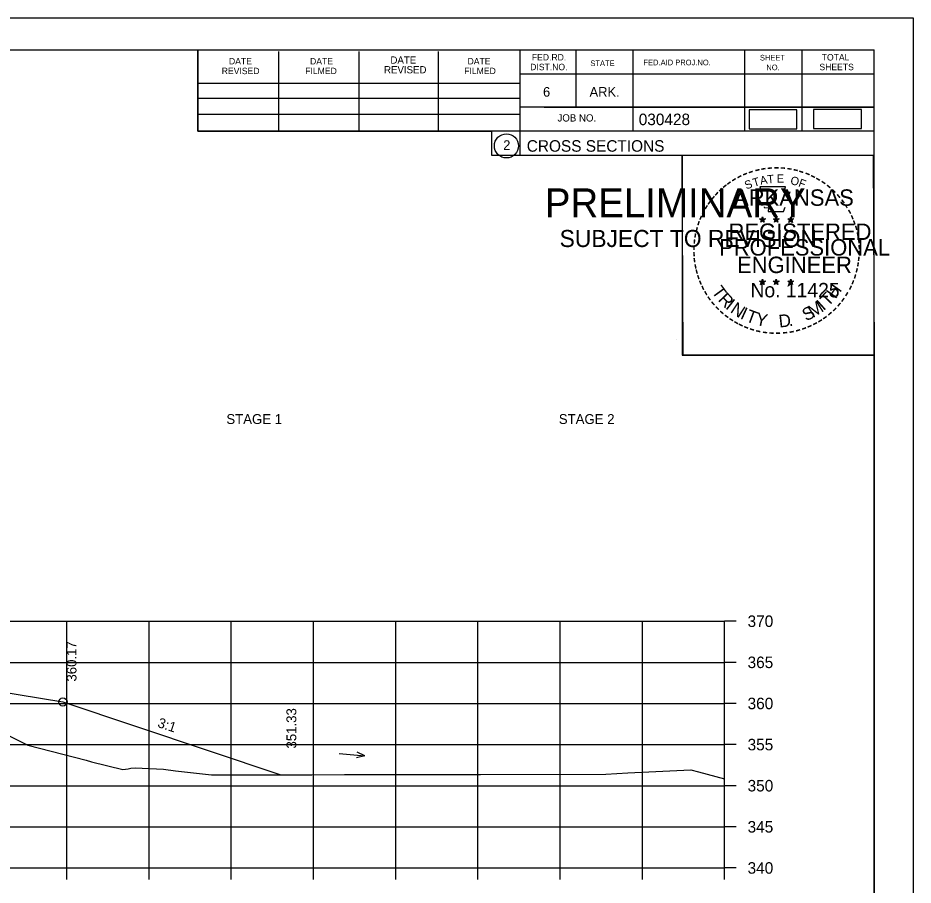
# Model space of a CAD drawing. Extents: x 1374859 to 1376773, y 382242 to 389804.
# Drawn here: x 1376188.6 to 1376297.5, y 385123 to 385228.5 of the extents above; entities that cross this region are included whole.
import ezdxf

# ---------------------------------------------------------------- set-up
doc = ezdxf.new("R2010")
doc.units = 0
for name, color, linetype in [('R_Axis', 7, 'Continuous'), ('R_Axis Annot', 7, 'Continuous'), ('R_Border', 7, 'Continuous'), ('R_Border PE', 7, 'Continuous'), ('R_Border Prem', 7, 'Continuous'), ('R_Exist Surface', 7, 'Continuous'), ('R_Fin Surface', 7, 'Continuous'), ('R_Grid', 7, 'Continuous'), ('R_MOT', 7, 'Continuous'), ('R_No Plot', 7, 'Continuous'), ('R_Water Annot', 7, 'Continuous'), ('R_Xsect Elev', 7, 'Continuous'), ('R_Xsect Slope', 7, 'Continuous')]:
    doc.layers.add(name, color=color, linetype=linetype)

msp = doc.modelspace()

# ---------------------------------------------------------------- linework, layer by layer
at = {"layer": 'R_Axis'}
for p, q in [((1376274.57, 385125.11), (1376274.57, 385155.11)), ((1376275.97, 385155.11), (1376274.57, 385155.11)), ((1376275.97, 385150.11), (1376274.57, 385150.11)), ((1376275.97, 385145.11), (1376274.57, 385145.11)), ((1376275.97, 385140.11), (1376274.57, 385140.11)), ((1376275.97, 385135.11), (1376274.57, 385135.11)), ((1376275.97, 385130.11), (1376274.57, 385130.11)), ((1375994.57, 385125.11), (1376274.57, 385125.11)), ((1376194.57, 385123.71), (1376194.57, 385125.11)), ((1376204.57, 385123.71), (1376204.57, 385125.11)), ((1376214.57, 385123.71), (1376214.57, 385125.11)), ((1376224.57, 385123.71), (1376224.57, 385125.11)), ((1376234.57, 385123.71), (1376234.57, 385125.11)), ((1376244.57, 385123.71), (1376244.57, 385125.11)), ((1376254.57, 385123.71), (1376254.57, 385125.11)), ((1376264.57, 385123.71), (1376264.57, 385125.11)), ((1376274.57, 385123.71), (1376274.57, 385125.11)), ((1376275.97, 385125.11), (1376274.57, 385125.11))]:
    msp.add_line(p, q, dxfattribs=at)
at = {"layer": 'R_Border'}
for p, q in [((1375976.57, 385224.57), (1376292.75, 385224.57)), ((1376210.49, 385214.69), (1376210.49, 385224.57)), ((1376220.35, 385214.69), (1376220.35, 385224.37)), ((1376230.11, 385214.69), (1376230.11, 385224.37)), ((1376239.79, 385214.69), (1376239.79, 385224.37)), ((1376249.65, 385224.57), (1376249.65, 385211.77)), ((1376256.49, 385224.57), (1376256.49, 385217.63)), ((1376263.43, 385224.57), (1376263.43, 385214.69)), ((1376277.01, 385224.57), (1376277.01, 385214.69)), ((1376283.95, 385224.57), (1376283.95, 385214.69)), ((1376292.75, 385019.11), (1376292.75, 385224.57)), ((1376292.75, 385221.63), (1376249.65, 385221.63)), ((1376292.75, 385221.65), (1376292.75, 385221.65)), ((1376210.49, 385220.55), (1376249.65, 385220.55)), ((1376210.49, 385218.69), (1376249.65, 385218.69)), ((1376292.75, 385217.63), (1376249.65, 385217.63)), ((1376252.61, 385217.63), (1376292.75, 385217.63)), ((1376210.49, 385214.69), (1376210.49, 385216.75)), ((1376210.49, 385216.75), (1376249.65, 385216.75)), ((1376292.75, 385214.69), (1376210.49, 385214.69)), ((1376249.65, 385211.77), (1376292.75, 385211.77))]:
    msp.add_line(p, q, dxfattribs=at)
msp.add_circle((1376248.04, 385212.91), 1.47, dxfattribs=at)
at = {"layer": 'R_Border PE'}
for p, q in [((1376279.18, 385204.28), (1376279.14, 385204.03)), ((1376279.18, 385203.92), (1376279.18, 385204.28)), ((1376279.18, 385204.28), (1376279.23, 385204.03)), ((1376280.85, 385204.28), (1376280.81, 385204.03)), ((1376280.85, 385203.92), (1376280.85, 385204.28)), ((1376280.85, 385204.28), (1376280.9, 385204.03)), ((1376282.62, 385204.27), (1376282.58, 385204.02)), ((1376282.62, 385203.91), (1376282.62, 385204.27)), ((1376282.62, 385204.27), (1376282.67, 385204.02)), ((1376278.84, 385204.03), (1376279.18, 385203.92)), ((1376278.84, 385204.03), (1376279.09, 385203.98)), ((1376278.84, 385204.03), (1376279.07, 385203.91)), ((1376278.97, 385203.62), (1376279.18, 385203.92)), ((1376278.97, 385203.62), (1376279.09, 385203.87)), ((1376278.97, 385203.62), (1376279.18, 385203.84)), ((1376279.53, 385204.03), (1376279.18, 385203.92)), ((1376279.4, 385203.62), (1376279.18, 385203.92)), ((1376279.4, 385203.62), (1376279.18, 385203.84)), ((1376279.53, 385204.03), (1376279.25, 385203.98)), ((1376279.4, 385203.62), (1376279.26, 385203.91)), ((1376279.53, 385204.03), (1376279.33, 385203.93)), ((1376280.51, 385204.03), (1376280.85, 385203.92)), ((1376280.51, 385204.03), (1376280.76, 385203.98)), ((1376280.51, 385204.03), (1376280.74, 385203.91)), ((1376280.64, 385203.62), (1376280.85, 385203.92)), ((1376280.64, 385203.62), (1376280.76, 385203.87)), ((1376280.64, 385203.62), (1376280.85, 385203.84)), ((1376281.2, 385204.03), (1376280.85, 385203.92)), ((1376281.07, 385203.62), (1376280.85, 385203.92)), ((1376281.07, 385203.62), (1376280.85, 385203.84)), ((1376281.2, 385204.03), (1376280.92, 385203.98)), ((1376281.07, 385203.62), (1376280.93, 385203.91)), ((1376281.2, 385204.03), (1376281, 385203.93)), ((1376282.27, 385204.02), (1376282.62, 385203.91)), ((1376282.27, 385204.02), (1376282.52, 385203.97)), ((1376282.27, 385204.02), (1376282.51, 385203.9)), ((1376282.4, 385203.61), (1376282.62, 385203.91)), ((1376282.4, 385203.61), (1376282.53, 385203.85)), ((1376282.4, 385203.61), (1376282.62, 385203.83)), ((1376282.97, 385204.02), (1376282.62, 385203.91)), ((1376282.83, 385203.61), (1376282.62, 385203.91)), ((1376282.83, 385203.61), (1376282.62, 385203.82)), ((1376282.97, 385204.02), (1376282.68, 385203.97)), ((1376282.83, 385203.61), (1376282.69, 385203.9)), ((1376282.97, 385204.02), (1376282.76, 385203.92)), ((1376279.18, 385196.71), (1376279.14, 385196.46)), ((1376279.18, 385196.35), (1376279.18, 385196.71)), ((1376279.18, 385196.71), (1376279.23, 385196.46)), ((1376280.85, 385196.71), (1376280.81, 385196.46)), ((1376280.85, 385196.35), (1376280.85, 385196.71)), ((1376280.85, 385196.71), (1376280.9, 385196.46)), ((1376282.62, 385196.7), (1376282.58, 385196.45)), ((1376282.62, 385196.34), (1376282.62, 385196.7)), ((1376282.62, 385196.7), (1376282.67, 385196.45)), ((1376278.83, 385196.46), (1376279.18, 385196.35)), ((1376278.83, 385196.46), (1376279.08, 385196.41)), ((1376278.83, 385196.46), (1376279.07, 385196.33)), ((1376278.96, 385196.05), (1376279.18, 385196.35)), ((1376278.96, 385196.05), (1376279.09, 385196.29)), ((1376278.96, 385196.05), (1376279.18, 385196.27)), ((1376279.53, 385196.46), (1376279.18, 385196.35)), ((1376279.39, 385196.05), (1376279.18, 385196.35)), ((1376279.39, 385196.05), (1376279.18, 385196.26)), ((1376279.53, 385196.46), (1376279.24, 385196.41)), ((1376279.39, 385196.05), (1376279.26, 385196.34)), ((1376279.53, 385196.46), (1376279.32, 385196.35)), ((1376280.5, 385196.46), (1376280.85, 385196.35)), ((1376280.5, 385196.46), (1376280.75, 385196.41)), ((1376280.5, 385196.46), (1376280.74, 385196.33)), ((1376280.63, 385196.05), (1376280.85, 385196.35)), ((1376280.63, 385196.05), (1376280.76, 385196.29)), ((1376280.63, 385196.05), (1376280.85, 385196.27)), ((1376281.2, 385196.46), (1376280.85, 385196.35)), ((1376281.06, 385196.05), (1376280.85, 385196.35)), ((1376281.06, 385196.05), (1376280.85, 385196.26)), ((1376281.2, 385196.46), (1376280.91, 385196.41)), ((1376281.06, 385196.05), (1376280.93, 385196.34)), ((1376281.2, 385196.46), (1376280.99, 385196.35)), ((1376282.27, 385196.45), (1376282.62, 385196.34)), ((1376282.27, 385196.45), (1376282.52, 385196.4)), ((1376282.27, 385196.45), (1376282.5, 385196.32)), ((1376282.4, 385196.04), (1376282.62, 385196.34)), ((1376282.4, 385196.04), (1376282.53, 385196.28)), ((1376282.4, 385196.04), (1376282.61, 385196.26)), ((1376282.83, 385196.04), (1376282.61, 385196.25)), ((1376282.96, 385196.45), (1376282.62, 385196.34)), ((1376282.83, 385196.04), (1376282.62, 385196.34)), ((1376282.96, 385196.45), (1376282.68, 385196.4)), ((1376282.83, 385196.04), (1376282.69, 385196.33)), ((1376282.96, 385196.45), (1376282.76, 385196.34))]:
    msp.add_line(p, q, dxfattribs=at)
for points in [[(1376278.88, 385207.91), (1376279.15, 385207.08)], [(1376282.39, 385206.99), (1376282.53, 385207.27), (1376281.84, 385207.25), (1376281.99, 385207.91), (1376278.88, 385207.91)], [(1376279.37, 385205.48), (1376279.37, 385205.4), (1376279.93, 385205.38), (1376279.88, 385204.91), (1376281.75, 385204.91), (1376281.95, 385205.44)], [(1376279.18, 385204.28), (1376279.4, 385203.62), (1376278.84, 385204.03), (1376279.53, 385204.03), (1376278.97, 385203.62), (1376279.18, 385204.28)], [(1376280.85, 385204.28), (1376281.07, 385203.62), (1376280.51, 385204.03), (1376281.2, 385204.03), (1376280.64, 385203.62), (1376280.85, 385204.28)], [(1376282.62, 385204.27), (1376282.83, 385203.61), (1376282.27, 385204.02), (1376282.97, 385204.02), (1376282.4, 385203.61), (1376282.62, 385204.27)], [(1376279.18, 385196.71), (1376279.39, 385196.05), (1376278.83, 385196.46), (1376279.53, 385196.46), (1376278.96, 385196.05), (1376279.18, 385196.71)], [(1376280.85, 385196.71), (1376281.06, 385196.05), (1376280.5, 385196.46), (1376281.2, 385196.46), (1376280.63, 385196.05), (1376280.85, 385196.71)], [(1376282.62, 385196.7), (1376282.83, 385196.04), (1376282.27, 385196.45), (1376282.96, 385196.45), (1376282.4, 385196.04), (1376282.62, 385196.7)]]:
    msp.add_lwpolyline(points, dxfattribs=at)
for centre, radius in [((1376279.18, 385203.92), 0.172), ((1376279.18, 385203.92), 0.145), ((1376279.18, 385203.92), 0.116), ((1376279.18, 385203.92), 0.0991), ((1376279.18, 385203.92), 0.0747), ((1376279.18, 385203.92), 0.0495), ((1376279.18, 385203.92), 0.0296), ((1376280.85, 385203.92), 0.172), ((1376280.85, 385203.92), 0.145), ((1376280.85, 385203.92), 0.116), ((1376280.85, 385203.92), 0.0991), ((1376280.85, 385203.92), 0.0747), ((1376280.85, 385203.92), 0.0495), ((1376280.85, 385203.92), 0.0296), ((1376282.62, 385203.91), 0.172), ((1376282.62, 385203.91), 0.145), ((1376282.62, 385203.91), 0.116), ((1376282.62, 385203.91), 0.0991), ((1376282.62, 385203.91), 0.0747), ((1376282.62, 385203.91), 0.0495), ((1376282.62, 385203.91), 0.0296), ((1376279.18, 385196.34), 0.172), ((1376279.18, 385196.34), 0.145), ((1376279.18, 385196.34), 0.116), ((1376279.18, 385196.34), 0.0991), ((1376279.18, 385196.34), 0.0747), ((1376279.18, 385196.34), 0.0495), ((1376279.18, 385196.34), 0.0296), ((1376280.85, 385196.34), 0.172), ((1376280.85, 385196.34), 0.145), ((1376280.85, 385196.34), 0.116), ((1376280.85, 385196.34), 0.0991), ((1376280.85, 385196.34), 0.0747), ((1376280.85, 385196.34), 0.0495), ((1376280.85, 385196.34), 0.0296), ((1376282.62, 385196.33), 0.172), ((1376282.62, 385196.33), 0.145), ((1376282.62, 385196.33), 0.116), ((1376282.62, 385196.33), 0.0991), ((1376282.62, 385196.33), 0.0747), ((1376282.62, 385196.33), 0.0495), ((1376282.62, 385196.33), 0.0296)]:
    msp.add_circle(centre, radius, dxfattribs=at)
at = {"layer": 'R_Exist Surface'}
msp.add_lwpolyline([(1376177.78, 385146.01), (1376189.81, 385140.03), (1376196.93, 385138.2), (1376197.58, 385138.03), (1376201.38, 385137.08), (1376202.02, 385137.18), (1376202.34, 385137.23), (1376202.86, 385137.28), (1376206.32, 385137.1), (1376207.77, 385136.93), (1376212.16, 385136.42), (1376224.37, 385136.45), (1376228.36, 385136.48), (1376241.87, 385136.48), (1376243.91, 385136.49), (1376244.88, 385136.48), (1376260.11, 385136.5), (1376262.79, 385136.66), (1376270.48, 385137.02), (1376271.42, 385136.78), (1376274.57, 385135.93)], dxfattribs=at)
at = {"layer": 'R_Fin Surface'}
msp.add_lwpolyline([(1376053.24, 385136.17), (1376059.15, 385134.2), (1376075.09, 385139.51), (1376083.13, 385140.85), (1376097.09, 385143.18), (1376105.09, 385143.79), (1376134.59, 385146.07), (1376164.09, 385148.34), (1376172.09, 385148.95), (1376185.9, 385146.65), (1376194.09, 385145.29), (1376220.61, 385136.44)], dxfattribs=at)
at = {"layer": 'R_Grid'}
for p, q in [((1375994.57, 385155.11), (1376274.57, 385155.11)), ((1376194.57, 385125.11), (1376194.57, 385155.11)), ((1376204.57, 385125.11), (1376204.57, 385155.11)), ((1376214.57, 385125.11), (1376214.57, 385155.11)), ((1376224.57, 385125.11), (1376224.57, 385155.11)), ((1376234.57, 385125.11), (1376234.57, 385155.11)), ((1376244.57, 385125.11), (1376244.57, 385155.11)), ((1376254.57, 385125.11), (1376254.57, 385155.11)), ((1376264.57, 385125.11), (1376264.57, 385155.11)), ((1376274.57, 385125.11), (1376274.57, 385155.11)), ((1375994.57, 385150.11), (1376274.57, 385150.11)), ((1375994.57, 385145.11), (1376274.57, 385145.11)), ((1375994.57, 385140.11), (1376274.57, 385140.11)), ((1375994.57, 385135.11), (1376274.57, 385135.11)), ((1375994.57, 385130.11), (1376274.57, 385130.11)), ((1375994.57, 385125.11), (1376274.57, 385125.11))]:
    msp.add_line(p, q, dxfattribs=at)
at = {"layer": 'R_MOT'}
for points in [[(1376277.55, 385215), (1376283.38, 385215), (1376283.38, 385217.31), (1376277.55, 385217.31)], [(1376285.38, 385215.02), (1376291.21, 385215.02), (1376291.21, 385217.33), (1376285.38, 385217.33)]]:
    msp.add_lwpolyline(points, close=True, dxfattribs=at)
at = {"layer": 'R_No Plot'}
for p, q in [((1375964.17, 385228.47), (1376297.5, 385228.47)), ((1376268.78, 385189.32), (1376268.78, 385189.32))]:
    msp.add_line(p, q, dxfattribs=at)
for points in [[(1375964.16, 385228.47), (1376297.5, 385228.47), (1376297.5, 385015.13), (1375964.16, 385015.13)], [(1376210.49, 385224.57), (1376210.49, 385214.69), (1376246.22, 385214.69), (1376246.22, 385211.77), (1376269.42, 385211.77), (1376269.42, 385187.44), (1376292.75, 385187.44), (1376292.75, 385019.11), (1375976.57, 385019.11), (1375976.57, 385224.57)], [(1376269.42, 385211.77), (1376292.63, 385211.77), (1376292.75, 385187.44), (1376269.54, 385187.44)]]:
    msp.add_lwpolyline(points, close=True, dxfattribs=at)
msp.add_circle((1376194.09, 385145.29), 0.5, dxfattribs=at)
at = {"layer": 'R_Water Annot'}
for p, q in [((1376227.68, 385139.04), (1376230.81, 385138.73)), ((1376230.81, 385138.73), (1376229.88, 385139.18)), ((1376230.81, 385138.73), (1376229.82, 385138.48))]:
    msp.add_line(p, q, dxfattribs=at)

# ---------------------------------------------------------------- texts
at = {"layer": 'R_Axis Annot'}
for s, p in [('STAGE 1', (1376213.97, 385179.09)), ('STAGE 2', (1376254.41, 385179.09))]:
    msp.add_text(s, height=1.2, rotation=360, dxfattribs=at).set_placement(p)
for s, p in [('370', (1376277.37, 385154.41)), ('365', (1376277.37, 385149.41)), ('360', (1376277.37, 385144.41)), ('355', (1376277.37, 385139.41)), ('350', (1376277.37, 385134.41)), ('345', (1376277.37, 385129.41)), ('340', (1376277.37, 385124.41))]:
    msp.add_text(s, height=1.4, dxfattribs=at).set_placement(p)
at = {"layer": 'R_Border'}
for s, height, p in [('FED.RD.', 0.782, (1376251.13, 385223.29)), ('SHEET', 0.684, (1376278.87, 385223.29)), ('TOTAL', 0.782, (1376286.39, 385223.29)), ('DATE', 0.782, (1376214.29, 385222.81)), ('DATE', 0.782, (1376224.15, 385222.81)), ('DATE', 0.879, (1376233.93, 385222.91)), ('DATE', 0.782, (1376243.31, 385222.81)), ('DIST.NO.', 0.782, (1376250.93, 385222.11)), ('STATE', 0.684, (1376258.25, 385222.61)), ('FED.AID PROJ.NO.', 0.684, (1376264.71, 385222.71)), ('NO.', 0.684, (1376279.65, 385222.11)), ('SHEETS', 0.782, (1376286.11, 385222.11)), ('REVISED', 0.782, (1376213.41, 385221.63)), ('FILMED', 0.782, (1376223.57, 385221.63)), ('REVISED', 0.879, (1376233.15, 385221.73)), ('FILMED', 0.782, (1376242.91, 385221.63)), ('6', 1.17, (1376252.49, 385218.89)), ('ARK.', 1.172, (1376258.15, 385218.89)), ('JOB NO.', 0.879, (1376254.25, 385215.87)), ('030428', 1.4, (1376264.13, 385215.43)), ('2', 1.17, (1376247.65, 385212.42)), ('CROSS SECTIONS', 1.4, (1376250.51, 385212.2))]:
    msp.add_text(s, height=height, rotation=360, dxfattribs=at).set_placement(p)
at = {"layer": 'R_Border PE'}
for s, height, rotation, p in [('-', 1.6, 24.3072, (1376276.99, 385208.77)), ('-', 1.6, 19.1761, (1376277.62, 385209.03)), ('-', 1.6, 13.6301, (1376278.37, 385209.28)), ('-', 1.6, 10.2193, (1376279.05, 385209.44)), ('-', 1.6, 5.8968, (1376279.78, 385209.55)), ('-', 1.6, 0.1862, (1376280.55, 385209.62)), ('-', 1.6, 357.743, (1376281.28, 385209.61)), ('-', 1.6, 352.1617, (1376282.02, 385209.55)), ('-', 1.6, 347.2049, (1376282.74, 385209.44)), ('-', 1.6, 342.3362, (1376283.37, 385209.28)), ('-', 1.6, 337.8551, (1376284.11, 385209.06)), ('-', 1.6, 36.2317, (1376275.18, 385207.68)), ('-', 1.6, 34.0636, (1376275.76, 385208.08)), ('-', 1.6, 28.7918, (1376276.36, 385208.45)), ('S', 1, 21.594, (1376277.23, 385207.59)), ('T', 1, 16.4036, (1376278.15, 385207.92)), ('A', 1, 11.2132, (1376278.97, 385208.17)), ('T', 1, 6.0228, (1376279.82, 385208.33)), ('E', 1, 0.8323, (1376280.93, 385208.44)), ('O', 1, 350.4515, (1376282.53, 385208.23)), ('F', 1, 340.0707, (1376283.48, 385208.01)), ('-', 1.6, 334.1211, (1376284.74, 385208.79)), ('-', 1.6, 329.6409, (1376285.32, 385208.5)), ('-', 1.6, 325.8627, (1376285.96, 385208.14)), ('-', 1.6, 42.9622, (1376274.27, 385206.89)), ('-', 1.6, 38.9507, (1376274.71, 385207.31)), ('ARKANSAS', 2, 360, (1376275.73, 385205.62)), ('-', 1.6, 320.5297, (1376286.57, 385207.72)), ('-', 1.6, 315.5786, (1376287.17, 385207.23)), ('-', 1.6, 50.6142, (1376273.42, 385205.92)), ('-', 1.6, 48.423, (1376273.83, 385206.41)), ('-', 1.6, 309.8797, (1376287.74, 385206.68)), ('-', 1.6, 306.6522, (1376288.27, 385206.08)), ('-', 1.6, 58.0706, (1376272.68, 385204.83)), ('-', 1.6, 54.2325, (1376273.01, 385205.36)), ('-', 1.4, 303.6753, (1376288.75, 385205.51)), ('-', 1.6, 67.7743, (1376272.11, 385203.61)), ('-', 1.6, 62.8713, (1376272.37, 385204.22)), ('-', 1.6, 299.6684, (1376289.07, 385204.9)), ('-', 1.6, 294.6628, (1376289.39, 385204.29)), ('-', 1.6, 72.3945, (1376271.89, 385202.98)), ('REGISTERED', 2, 360, (1376275.05, 385201.47)), ('DWB', 0.01, 360, (1376279.17, 385203.91)), ('DWB', 0.01, 360, (1376280.84, 385203.91)), ('DWB', 0.01, 360, (1376282.61, 385203.9)), ('-', 1.6, 290.5728, (1376289.65, 385203.71)), ('-', 1.6, 285.1233, (1376289.89, 385203.13)), ('-', 1.6, 81.2013, (1376271.56, 385201.55)), ('-', 1.6, 75.461, (1376271.7, 385202.26)), ('-', 1.6, 280.5493, (1376290.09, 385202.39)), ('-', 1.6, 85.1863, (1376271.49, 385200.86)), ('PROFESSIONAL', 2, 360, (1376273.9, 385199.57)), ('-', 1.6, 276.5962, (1376290.25, 385201.62)), ('-', 1.6, 94.1959, (1376271.5, 385199.43)), ('-', 1.6, 89.0622, (1376271.46, 385200.16)), ('-', 1.6, 274.3301, (1376290.31, 385200.9)), ('-', 1.6, 269.9407, (1376290.34, 385200.27)), ('-', 1.6, 98.9479, (1376271.57, 385198.76)), ('ENGINEER', 2, 360, (1376276.09, 385197.44)), ('-', 1.6, 260.9953, (1376290.25, 385198.95)), ('-', 1.6, 263.5172, (1376290.32, 385199.6)), ('-', 1.6, 101.7149, (1376271.71, 385198.03)), ('-', 1.6, 105.4578, (1376271.87, 385197.44)), ('-', 1.6, 255.7626, (1376290.14, 385198.27)), ('-', 1.6, 109.0874, (1376272.08, 385196.81)), ('-', 1.6, 247.8887, (1376289.74, 385196.88)), ('-', 1.6, 252.8681, (1376289.96, 385197.55)), ('-', 1.6, 114.0643, (1376272.34, 385196.21)), ('-', 1.6, 115.7289, (1376272.64, 385195.59)), ('T', 1.54, 306.0406, (1376272.94, 385195.18)), ('No. 11425', 1.757, 360, (1376277.72, 385194.49)), ('DWB', 0.01, 360, (1376279.17, 385196.34)), ('DWB', 0.01, 360, (1376280.84, 385196.34)), ('DWB', 0.01, 360, (1376282.6, 385196.33)), ('H', 1.54, 54.6088, (1376288.06, 385194.22)), ('-', 1.6, 244.6197, (1376289.48, 385196.25)), ('-', 1.6, 120.4471, (1376273, 385195.01)), ('-', 1.6, 125.8934, (1376273.4, 385194.44)), ('R', 1.54, 314.005, (1376273.7, 385194.14)), ('T', 1.54, 46.6444, (1376287.17, 385193.28)), ('-', 1.6, 233.8452, (1376288.68, 385194.84)), ('-', 1.6, 239.0712, (1376289.08, 385195.5)), ('-', 1.6, 130.7181, (1376273.86, 385193.89)), ('-', 1.6, 134.2238, (1376274.38, 385193.35)), ('I', 1.54, 321.9694, (1376274.6, 385193.2)), ('N', 1.54, 326.5002, (1376275.17, 385192.73)), ('S', 1.54, 26.9312, (1376284.49, 385191.55)), ('M', 1.54, 32.6563, (1376285.32, 385191.95)), ('I', 1.54, 42.1136, (1376286.61, 385192.8)), ('-', 1.6, 231.2538, (1376288.25, 385194.28)), ('-', 1.6, 138.9338, (1376274.91, 385192.88)), ('-', 1.6, 144.6463, (1376275.46, 385192.48)), ('I', 1.54, 335.3603, (1376276.38, 385191.95)), ('T', 1.54, 339.8912, (1376277.04, 385191.62)), ('Y', 1.54, 347.8556, (1376278.26, 385191.17)), ('D', 1.54, 6.3969, (1376281.24, 385190.81)), ('-', 1.6, 215.7363, (1376286.7, 385192.73)), ('-', 1.6, 221.0851, (1376287.25, 385193.21)), ('-', 1.6, 225.7653, (1376287.77, 385193.71)), ('-', 1.6, 148.0898, (1376276.02, 385192.11)), ('-', 1.6, 151.5704, (1376276.6, 385191.78)), ('-', 1.6, 154.6002, (1376277.12, 385191.53)), ('.', 1.54, 13.7642, (1376282.43, 385190.94)), ('-', 1.6, 204.2516, (1376284.98, 385191.68)), ('-', 1.6, 207.3568, (1376285.61, 385192)), ('-', 1.6, 212.2491, (1376286.17, 385192.35)), ('-', 1.6, 158.5612, (1376277.75, 385191.28)), ('-', 1.6, 162.7983, (1376278.43, 385191.07)), ('-', 1.6, 167.5555, (1376279.15, 385190.9)), ('-', 1.6, 173.1155, (1376279.92, 385190.79)), ('-', 1.6, 176.5183, (1376280.67, 385190.74)), ('-', 1.6, 181.5918, (1376281.41, 385190.76)), ('-', 1.6, 185.8167, (1376282.22, 385190.84)), ('-', 1.6, 191.2858, (1376282.96, 385190.97)), ('-', 1.6, 195.4743, (1376283.69, 385191.17)), ('-', 1.6, 200.7184, (1376284.36, 385191.41))]:
    msp.add_text(s, height=height, rotation=rotation, dxfattribs=at).set_placement(p)
at = {"layer": 'R_Border Prem'}
for s, height, p in [('PRELIMINARY', 3.5, (1376252.7, 385204.24)), ('DWB', 0.01, (1376253.45, 385206.09)), ('SUBJECT TO REVISION', 2.0751, (1376254.51, 385200.61))]:
    msp.add_text(s, height=height, rotation=360, dxfattribs=at).set_placement(p)
at = {"layer": 'R_Xsect Elev'}
for s, p in [('360.17', (1376195.74, 385147.77)), ('351.33', (1376222.48, 385139.63))]:
    msp.add_text(s, height=1.2, rotation=90, dxfattribs=at).set_placement(p)
at = {"layer": 'R_Xsect Slope'}
msp.add_text('3:1', height=1.2, rotation=341.5651, dxfattribs=at).set_placement((1376205.52, 385142.27))

doc.saveas('drawing.dxf')
